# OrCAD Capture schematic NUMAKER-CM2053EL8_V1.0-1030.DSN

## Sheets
1 Nu-Link2-Me: size A3; title: Nu-Link2-Me; rev: 1.1; company: HCTu; note: Nu-Link2-Me
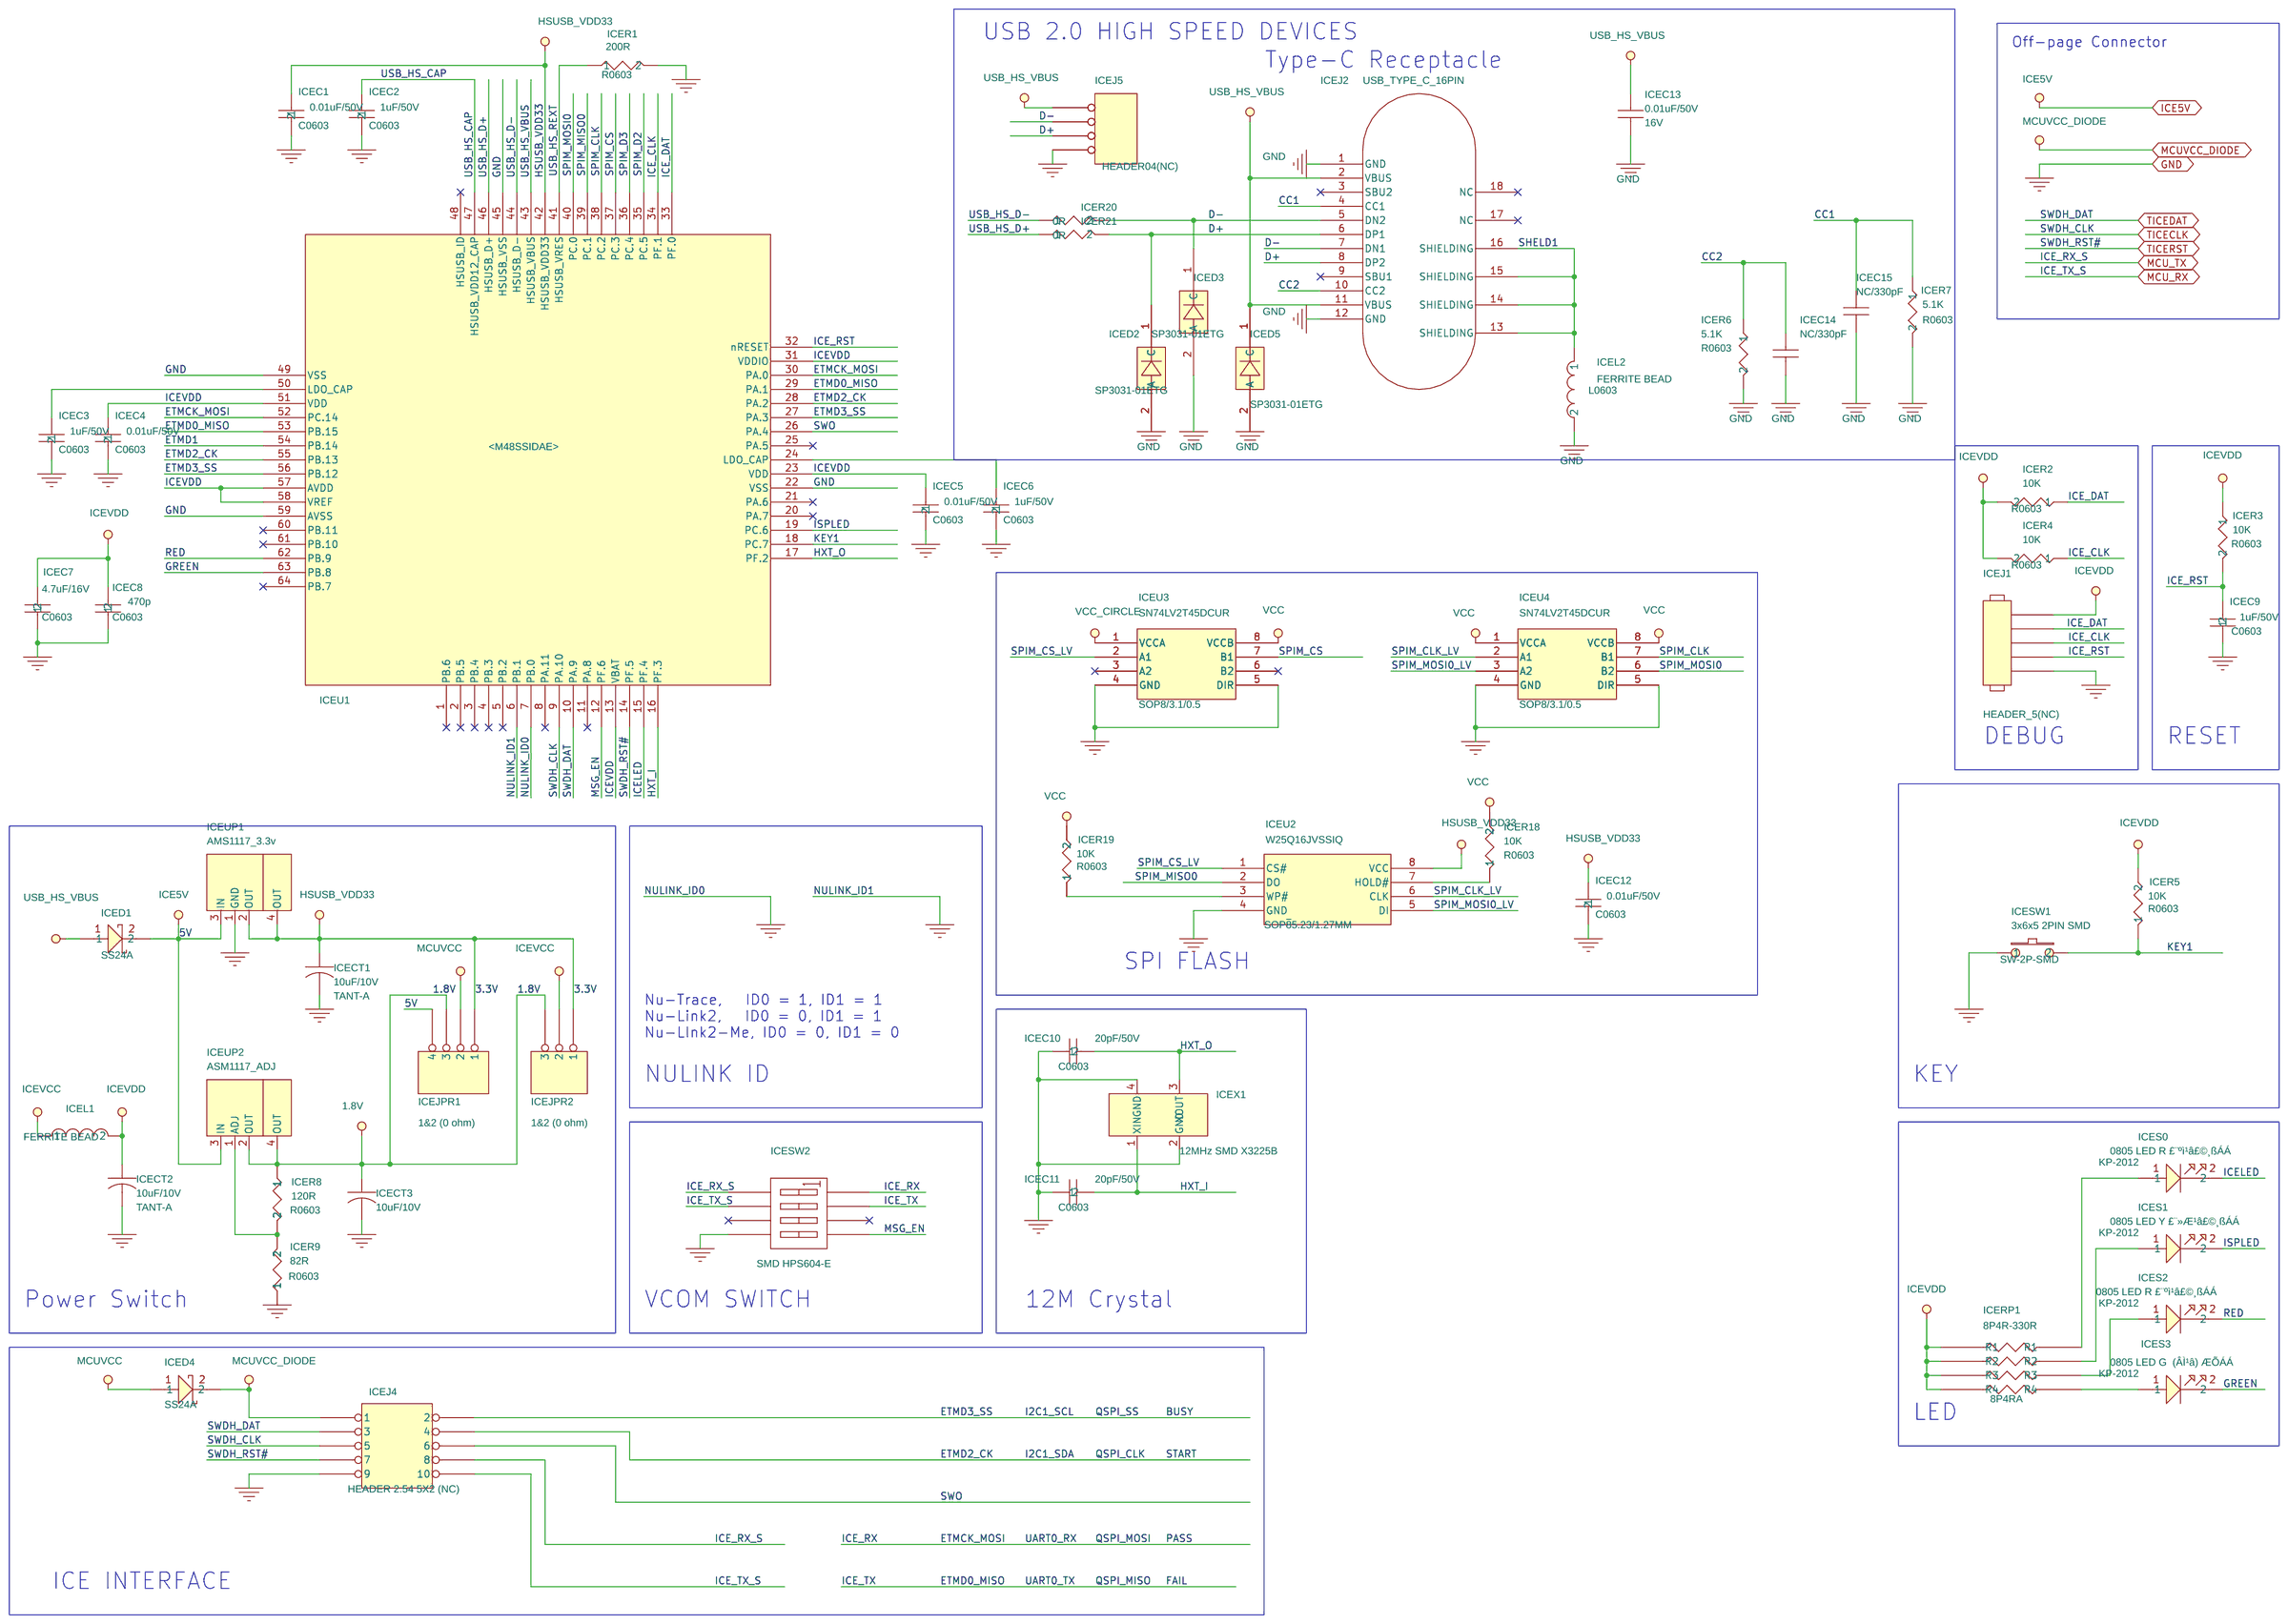
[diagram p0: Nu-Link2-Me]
2 CM2053EL8AE: size Custom; title: CM2053EL8AE; rev: v1.0; note: NuMaker-CM2053EL8
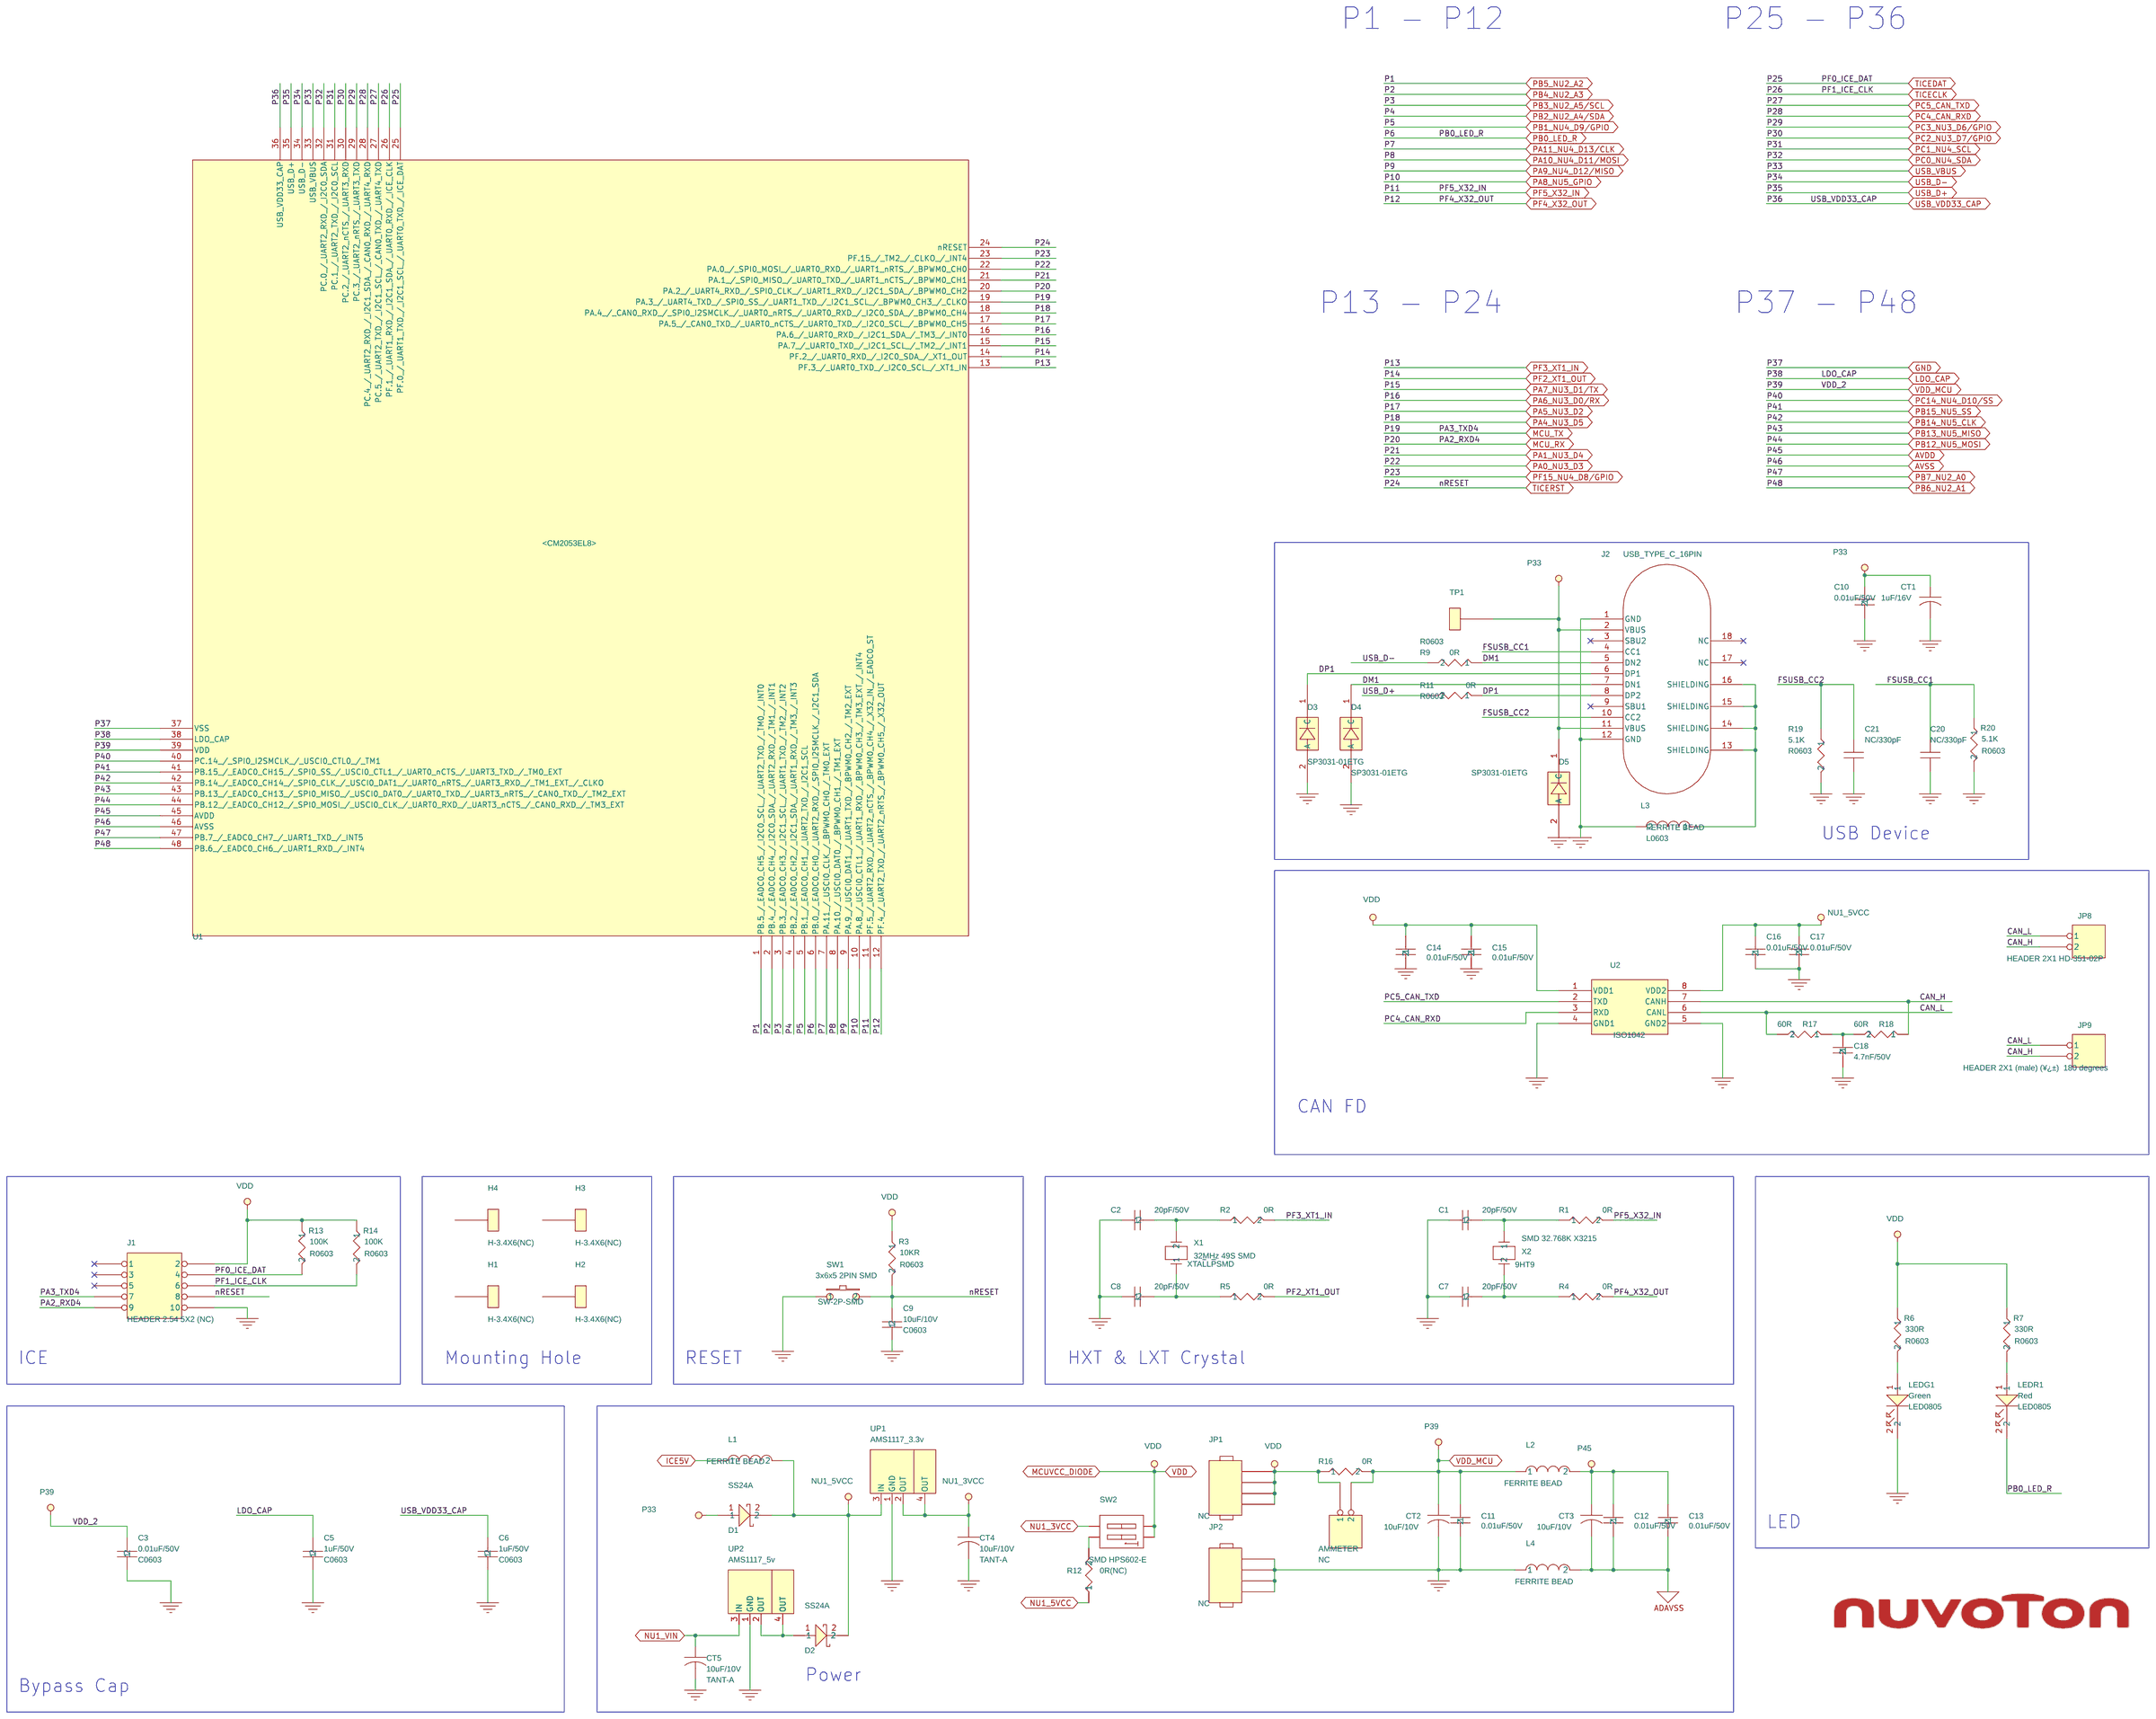
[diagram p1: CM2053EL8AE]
3 Ext. Connector: size Custom; title: Ext. Connector; rev: v1.0; note: NuMaker-CM2053EL8
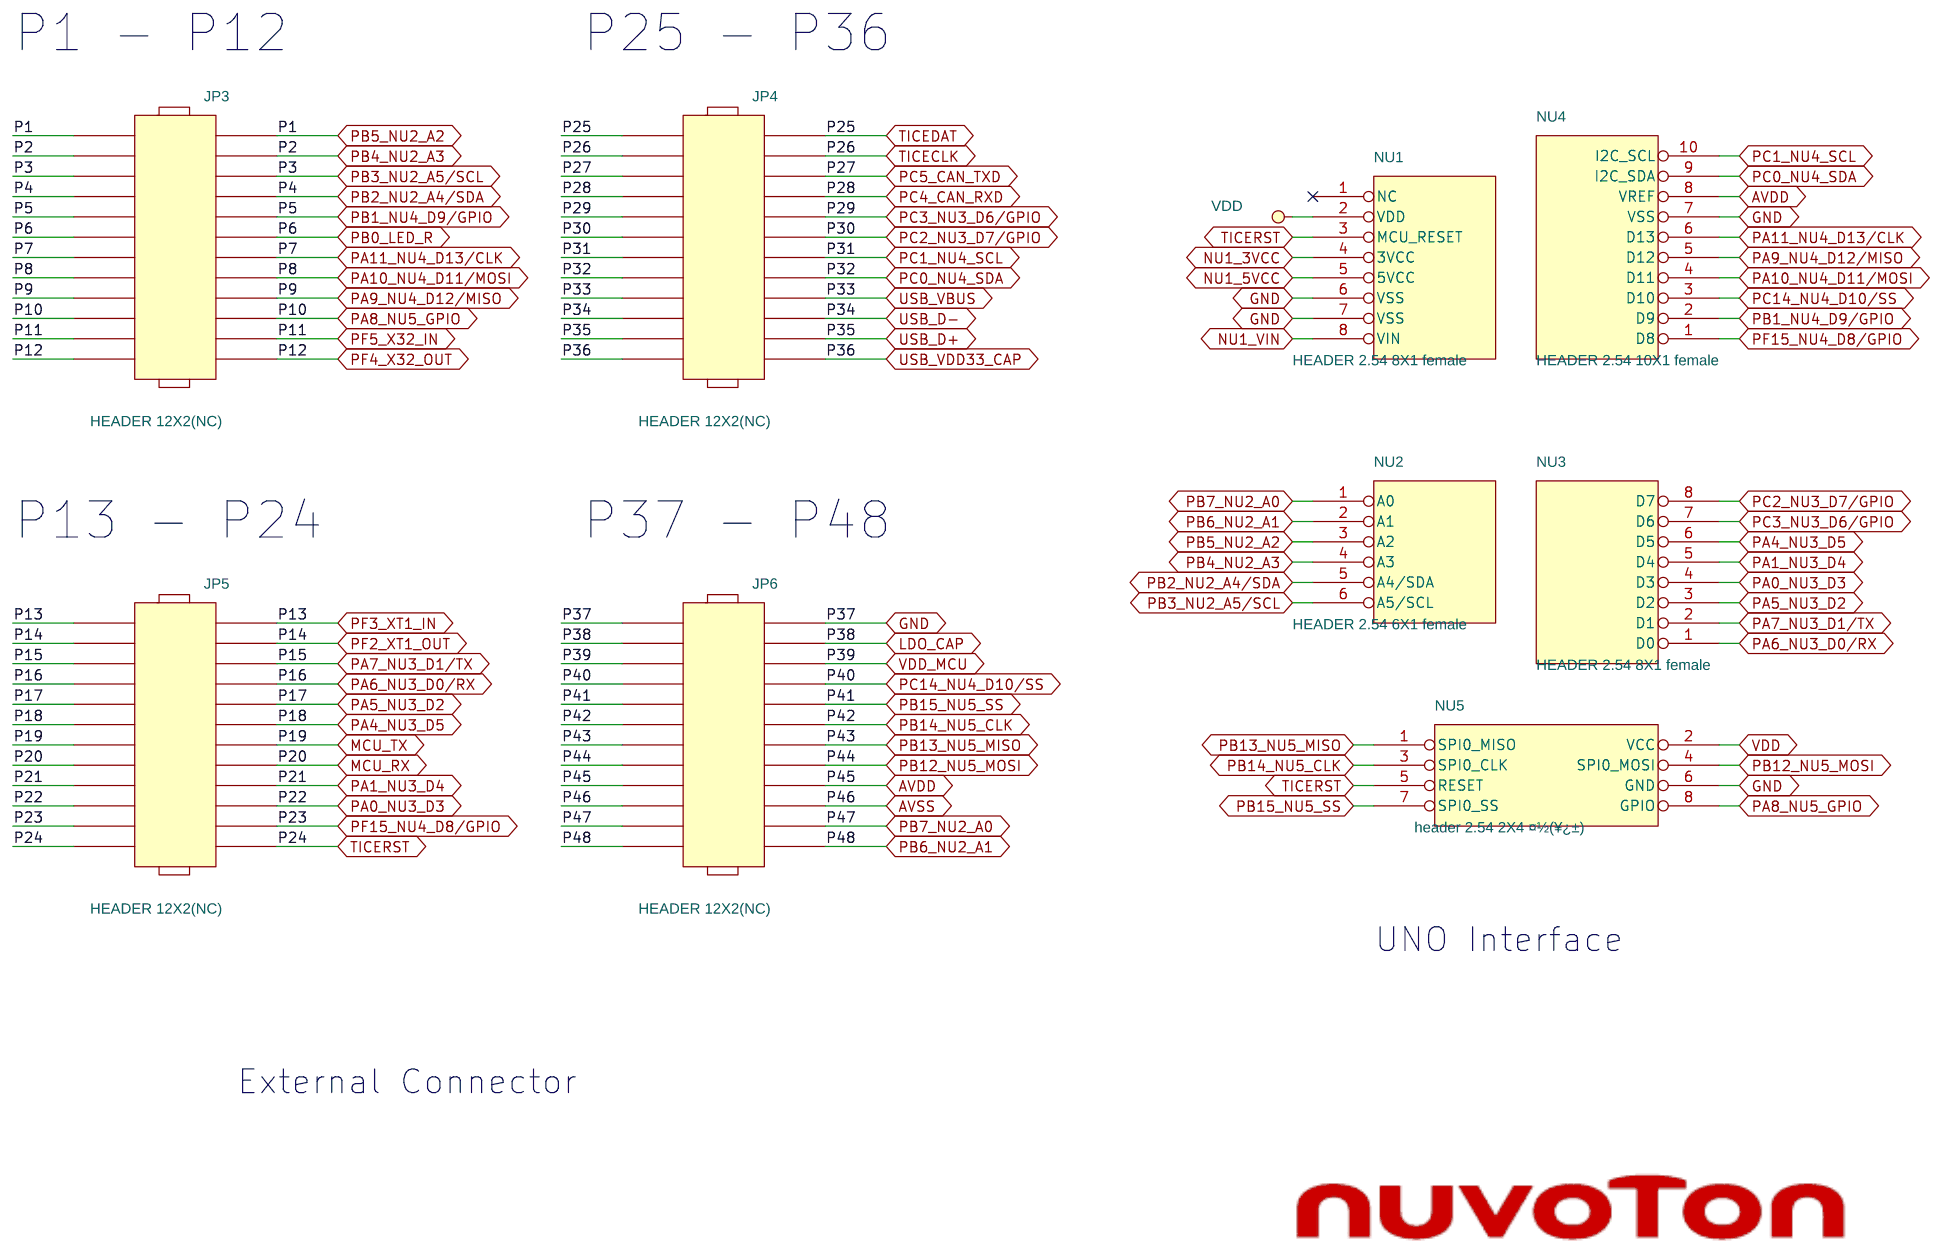
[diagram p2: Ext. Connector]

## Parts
sheet CM2053EL8AE
AMMETER  NC  [HEADER2X1]
C1  20pF/50V  [C0603]
C2  20pF/50V  [C0603]
C3  0.01uF/50V  [C0603]
C5  1uF/50V  [C0603]
C6  1uF/50V  [C0603]
C7  20pF/50V  [C0603]
C8  20pF/50V  [C0603]
C9  10uF/10V  [C0603]
C10  0.01uF/50V  [C0603]
C11  0.01uF/50V  [C0603]
C12  0.01uF/50V  [C0603]
C13  0.01uF/50V  [C0603]
C14  0.01uF/50V  [C0603]
C15  0.01uF/50V  [C0603]
C16  0.01uF/50V  [C0603]
C17  0.01uF/50V  [C0603]
C18  4.7nF/50V  [C0603]
C20  NC/330pF  [C0603]
C21  NC/330pF  [C0603]
CT1  1uF/16V  [TANT-A]
CT2  10uF/10V  [TANT-A]
CT3  10uF/10V  [TANT-A]
CT4  10uF/10V  [TANT-A]
CT5  10uF/10V  [TANT-A]
D1  SS24A  [RB060L]
D2  SS24A  [RB060L]
D3  SP3031-01ETG  [SOD882]
D4  SP3031-01ETG  [SOD882]
D5  SP3031-01ETG  [SOD882]
H1  H-3.4X6(NC)  [H-3.4X6]
H2  H-3.4X6(NC)  [H-3.4X6]
H3  H-3.4X6(NC)  [H-3.4X6]
H4  H-3.4X6(NC)  [H-3.4X6]
J1  HEADER 2.54 5X2 (NC)  [HEADER5X2]
J2  USB_TYPE_C_16PIN  [TID(00302-UCAF003-N)]
JP1  NC  [header1x4]
JP2  NC  [header1x4]
JP8  HEADER 2X1 HD-351-02P  [SIP/2P_3.5MM]
JP9  HEADER 2X1 (male) (¥¿­±)  180 degrees  [SIP-2P]
L1  FERRITE BEAD  [L0603]
L2  FERRITE BEAD  [L0603]
L3  FERRITE BEAD  [L0603]
L4  FERRITE BEAD  [L0603]
LEDG1  Green  [LED0805]
LEDR1  Red  [LED0805]
R1  0R  [R0603]
R2  0R  [R0603]
R3  10KR  [R0603]
R4  0R  [R0603]
R5  0R  [R0603]
R6  330R  [R0603]
R7  330R  [R0603]
R9  0R  [R0603]
R11  0R  [R0603]
R12  0R(NC)  [R0603]
R13  100K  [R0603]
R14  100K  [R0603]
R16  0R  [R0603]
R17  60R  [R0603]
R18  60R  [R0603]
R19  5.1K  [R0603]
R20  5.1K  [R0603]
SW1  3x6x5 2PIN SMD  [SW-2P-SMD]
SW2  SMD HPS602-E  [SW1X2]
TP1  TEST_POINT  [TEST_POINT]
U1  CM2053EL8  [MCU_LQFP_48]
U2  ISO1042  [SOIC-2.8MM]
UP1  AMS1117_3.3v  [SOT-223-1]
UP2  AMS1117_5v  [SOT-223-1]
X1  32MHz 49S SMD  [XTAL\LP\SMD]
X2  SMD 32.768K X3215  [9HT9]
sheet Ext. Connector
JP3  HEADER 12X2(NC)  [HEADER12x2/2.54]
JP4  HEADER 12X2(NC)  [HEADER12x2/2.54]
JP5  HEADER 12X2(NC)  [HEADER12x2/2.54]
JP6  HEADER 12X2(NC)  [HEADER12x2/2.54]
NU1  HEADER 2.54 8X1 female  [SIP-8P]
NU2  HEADER 2.54 6X1 female  [SIP-6P]
NU3  HEADER 2.54 8X1 female  [SIP-8P]
NU4  HEADER 2.54 10X1 female  [SIP-10P]
NU5  header 2.54 2X4 ¤½(¥¿­±)  [HEADER4X2]
sheet Nu-Link2-Me
ICEC1  0.01uF/50V  [C0603]
ICEC2  1uF/50V  [C0603]
ICEC3  1uF/50V  [C0603]
ICEC4  0.01uF/50V  [C0603]
ICEC5  0.01uF/50V  [C0603]
ICEC6  1uF/50V  [C0603]
ICEC7  4.7uF/16V  [C0603]
ICEC8  470p  [C0603]
ICEC9  1uF/50V  [C0603]
ICEC10  20pF/50V  [C0603]
ICEC11  20pF/50V  [C0603]
ICEC12  0.01uF/50V  [C0603]
ICEC13  0.01uF/50V  [C0603]
ICEC14  NC/330pF  [C0603]
ICEC15  NC/330pF  [C0603]
ICECT1  10uF/10V  [TANT-A]
ICECT2  10uF/10V  [TANT-A]
ICECT3  10uF/10V  [TANT-A]
ICED1  SS24A  [RB060L]
ICED2  SP3031-01ETG  [SOD882]
ICED3  SP3031-01ETG  [SOD882]
ICED4  SS24A  [RB060L]
ICED5  SP3031-01ETG  [SOD882]
ICEJ1  HEADER_5(NC)  [HEADER5X1]
ICEJ2  USB_TYPE_C_16PIN  [TID(00302-UCAF003-N)]
ICEJ4  HEADER 2.54 5X2 (NC)  [HEADER5X2]
ICEJ5  HEADER04(NC)  [HEADER04]
ICEJPR1  1&2 (0 ohm)  [R0603X3]
ICEJPR2  1&2 (0 ohm)  [R0603X2]
ICEL1  FERRITE BEAD  [L0603]
ICEL2  FERRITE BEAD  [L0603]
ICER1  200R  [R0603]
ICER2  10K  [R0603]
ICER3  10K  [R0603]
ICER4  10K  [R0603]
ICER5  10K  [R0603]
ICER6  5.1K  [R0603]
ICER7  5.1K  [R0603]
ICER8  120R  [R0603]
ICER9  82R  [R0603]
ICER18  10K  [R0603]
ICER19  10K  [R0603]
ICER20  0R  [R0603]
ICER21  0R  [R0603]
ICERP1  8P4R-330R  [8P4RA]
ICES0  0805 LED R £¨ºì¹â£©¸ßÁÁ  [KP-2012]
ICES1  0805 LED Y £¨»Æ¹â£©¸ßÁÁ  [KP-2012]
ICES2  0805 LED R £¨ºì¹â£©¸ßÁÁ  [KP-2012]
ICES3  0805 LED G  (ÂÌ¹â) ÆÕÁÁ  [KP-2012]
ICESW1  3x6x5 2PIN SMD  [SW-2P-SMD]
ICESW2  SMD HPS604-E  [SW1X4]
ICEU1  M48SSIDAE  [LQFP64_7x7_M48SSIDAE]
ICEU2  W25Q16JVSSIQ  [SOP8\5.23/1.27MM]
ICEU3  SN74LV2T45DCUR  [SOP8/3.1/0.5]
ICEU4  SN74LV2T45DCUR  [SOP8/3.1/0.5]
ICEUP1  AMS1117_3.3v  [SOT-223-1]
ICEUP2  ASM1117_ADJ  [SOT-223-1]
ICEX1  12MHz SMD X3225B  [CRYSTAL_SMD]

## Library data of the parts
AMMETER = HEADER_2_2
C1 = C_20p_2
C2 = C_20p
C3 = CAP-C_2: Package: 0603; element_no: C0004
C5 = CAP-C_1: Package: 0603; element_no: C0006
C6 = CAP-C: Package: 0603; element_no: C0006
C7 = C_20p_1
C8 = C_20p_3
C9 ICEC6 = CAP-C_3: Package: 0603; element_no: C0006
C10 = C_0.1u_6: element_no: C0004
C11 = C_0.1u: element_no: C0004
C12 = C_0.1u_2: element_no: C0004
C13 = C_0.1u_8: element_no: C0003
C14 = C_0.1u_3: element_no: C0004
C15 = C_0.1u_7: element_no: C0003
C16 = C_0.1u_1: element_no: C0004
C17 = C_0.1u_4: element_no: C0003
C18 = C_0.1u_5: element_no: C0003
C20 C21 ICEC14 ICEC15 = CAPACITOR_NP: CAP CER NPO SMD 330pF 5% 50V 0603; Mount: M; Part Number: 880600252; Part Type: Capacitor\Ceramic; Raing/Power: 50V; Tolerance: 5%
CT1 = C_1uF_16V
CT2-CT5 ICECT1-ICECT3 = C_10uF_10V
D1 ICED1 = D_SS24A
D2 ICED4 = D_SS24A_1
D3-D5 ICED2 ICED3 ICED5 = Schottky_Barrier_Diode_1: Diode SMD Schottky Barrier 30V; Mount: M; Part Number: 880900908
H1-H4 TP1 = TEST_POINT
ICEJ4 J1 = HEADER_5X2
ICEJ2 J2 = USB_TYPE_C_10: CON USB 3.0 Type C receptical SMD & TH; Mount: M; Part Number: 880400981; Part Type: Connector
JP1 JP2 = HEADER_4_v2
JP8 = HEADER_2_1
JP9 = HEADER_2
L1 = FERRITE_BEAD_2
L2 = FERRITE_BEAD_3
ICEL2 L3 = FERRITE_BEAD
ICEL1 L4 = FERRITE_BEAD_1
LEDG1 = LED_0_1: Package: KP-2012; Vendor: Kingbright
LEDR1 = LED_0: Package: KP-2012; Vendor: Kingbright
R1 = R_0_13
R2 = R_0_1
ICER8 R3 = R_0_3: Package: 0603
R4 = R_0_10
R5 = R_0_14
ICER3 R6 = R_0_6: Package: 0603
ICER5 R7 = R_0: Package: 0603
R9 = R_0_9
R11 = R_0_11
R12 = R_0_2
ICER1 R13 = R_0_5: Package: 0603
ICER18 R14 = R_0_7: Package: 0603
R16 = R_0_12
ICER20 R17 = R_33_1
ICER21 R18 = R_33
ICER6 R19 = R_0_4: Package: 0603
ICER7 R20 = R_0_8: Package: 0603
ICESW1 SW1 = SW_PUSHBUTTON_0
SW2 = SW_DIP-4_2
U1 = M032LD2AE_1: M032LD2AE: <CM2053EL8>
U2 = ADM3050
ICEUP1 UP1 UP2 = TO-247_Regulator_10
X1 = Xtal_12MHz
X2 = Xtal_32.768K
JP3-JP6 = HEADER_12X2
NU1 = POWER_CONNECT_0
NU2 = ADC_CONNECT_0
NU3 = PWM0_CONNECT_0
NU4 = PWM1_CONNECT_1
NU5 = NuEdu_NU7
ICEC1 = CAP-C_8: Package: 0603; element_no: C0004
ICEC2 = CAP-C_9: Package: 0603; element_no: C0006
ICEC3 = CAP-C_11: Package: 0603; element_no: C0006
ICEC4 = CAP-C_1: Package: 0603; element_no: C0004
ICEC5 = CAP-C_4: Package: 0603; element_no: C0004
ICEC7 = CAP-C: Package: 0603
ICEC8 = CAP-C_6: Package: 0603
ICEC9 = CAP-C_5: Package: 0603; element_no: C0006
ICEC10 = CAP-C_2: Package: 0603
ICEC11 = CAP-C_10: Package: 0603
ICEC12 = CAP-C_7: Package: 0603; element_no: C0004
ICEC13 = CAPACITOR_NP: CAP CER X7R SMD 0.1uF 10% 50V 0603; Mount: M; Part Number: 880600286; Part Type: Capacitor\Ceramic; Raing/Power: 16V; Tolerance: 10%
ICEJ1 = HEADER_5
ICEJ5 = HEADER_4
ICEJPR1 = HEADER_3_0
ICEJPR2 = HEADER_3
ICER2 = R_0_2: Package: 0603
ICER4 = R_0_9: Package: 0603
ICER9 = R_0_10: Package: 0603
ICER19 = R_0_1: Package: 0603
ICERP1 = R-PACK8_0
ICES0 = LED_0_3: Vendor: Kingbright
ICES1 = LED_0: Vendor: Kingbright
ICES2 = LED_0_1: Vendor: Kingbright
ICES3 = LED_0_2: Vendor: Kingbright
ICESW2 = SW_DIP-4_SM
ICEU1 = M487SIDAE_0: M487SIDAE: <M48SSIDAE>
ICEU2 = W25P10_20_40_SOIC_0: Package: SOP8; Vendor: WINBOND
ICEU3 ICEU4 = SN74LV2T45
ICEUP2 = TO-247_Regulator_0
ICEX1 = Crystal_SMD_1

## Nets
1.8V: ICECT3.1 ICEJPR1.3 ICEJPR2.3 ICER8.1 ICEUP2.2(OUT) ICEUP2.4(OUT)
3.3V: ICEC1.1 ICEC12.1 ICECT1.1 ICEJPR1.1 ICEJPR2.1 ICER18.2 ICER19.2 ICEU1.42(HSUSB_VDD33) ICEU2.8(VCC) ICEU3.1(VCCA) ICEU4.1(VCCA) ICEUP1.2(OUT) ICEUP1.4(OUT)
AVDD: C12.1 C13.1 CT3.1 JP6.17 JP6.18 L2.2 NU4.8(VREF) U1.45(AVDD)
AVSS: C12.2 C13.2 CT3.2 JP6.19 JP6.20 L4.2 U1.46(AVSS)
GND: C1.1 C2.1 C3.1 C5.1 C6.1 C7.1 C8.1 C9.1 C10.2 C11.2 C14.2 C15.2 C16.2 C17.2 C18.2 C20.2 C21.2 CT1.2 CT2.2 CT4.2 CT5.2 D3.2(A) D4.2(A) D5.2(A) ICEC1.2 ICEC2.2 ICEC3.2 ICEC4.2 ICEC5.2 ICEC6.2 ICEC7.1 ICEC8.1 ICEC9.1 ICEC10.1 ICEC11.1 ICEC12.2 ICEC13.2 ICEC14.2 ICEC15.2 ICECT1.2 ICECT2.2 ICECT3.2 ICED2.2(A) ICED3.2(A) ICED5.2(A) ICEJ1.5 ICEJ2.1(GND) ICEJ2.12(GND) ICEJ4.9 ICEJ5.4 ICEL2.2 ICER1.2 ICER6.2 ICER7.2 ICER9.1 ICESW1.1 ICESW2.4(A4) ICEU1.6(PB.1) ICEU1.7(PB.0) ICEU1.22(VSS) ICEU1.45(HSUSB_VSS) ICEU1.49(VSS) ICEU1.59(AVSS) ICEU2.4(GND) ICEU3.4(GND) ICEU3.5(DIR) ICEU4.4(GND) ICEU4.5(DIR) ICEUP1.1(GND) ICEX1.2(GND) ICEX1.4(GND) J1.10 J2.1(GND) J2.12(GND) JP2.1 JP2.2 JP2.3 JP2.4 JP6.1 JP6.2 L3.2 L4.1 LEDG1.2 NU1.6(VSS) NU1.7(VSS) NU4.7(VSS) NU5.6(GND) R19.2 R20.2 SW1.1 U1.37(VSS) U2.4(GND1) U2.5(GND2) UP1.1(GND) UP2.1(GND)
VDD: AMMETER.1 C14.1 C15.1 ICED4.2 ICEJ4.1 J1.2 JP1.1 JP1.2 JP1.3 JP1.4 NU1.2(VDD) NU5.2(VCC) R3.1 R6.1 R7.1 R13.1 R14.1 R16.1 SW2.3(B1) SW2.4(B2) U2.1(VDD1)
VDD_MCU: AMMETER.2 C3.2 C11.1 CT2.1 JP6.5 JP6.6 L2.1 R16.2 U1.39(VDD)
BUSY: ICEJ4.2 ICEU1.27(PA.3) ICEU1.56(PB.12)
CAN_H: JP8.2 JP9.2 R18.1 U2.7(CANH)
CAN_L: JP8.1 JP9.1 R17.2 U2.6(CANL)
CC1: ICEC15.1 ICEJ2.4(CC1) ICER7.1
CC2: ICEC14.1 ICEJ2.10(CC2) ICER6.1
D+: ICED2.1(C) ICEJ2.6(DP1) ICEJ2.8(DP2) ICEJ5.3 ICER21.2
D-: ICED3.1(C) ICEJ2.5(DN2) ICEJ2.7(DN1) ICEJ5.2 ICER20.2
DM1: D4.1(C) J2.5(DN2) J2.7(DN1) R9.1
DP1: D3.1(C) J2.6(DP1) J2.8(DP2) R11.1
ETMD1: ICEU1.54(PB.14)
ETMD2_CK: ICEJ4.4 ICEU1.28(PA.2) ICEU1.55(PB.13)
FSUSB_CC1: C20.1 J2.4(CC1) R20.1
FSUSB_CC2: C21.1 J2.10(CC2) R19.1
GREEN: ICES3.2 ICEU1.63(PB.8)
HXT_I: ICEC11.2 ICEU1.16(PF.3) ICEX1.1(XIN)
HXT_O: ICEC10.2 ICEU1.17(PF.2) ICEX1.3(XOUT)
ICE5V: ICED1.2 ICEJPR1.4 ICEUP1.3(IN) ICEUP2.3(IN) L1.1
ICE_CLK: ICEJ1.3 ICER4.1 ICEU1.34(PF.1)
ICE_DAT: ICEJ1.2 ICER2.1 ICEU1.33(PF.0)
ICE_RST: ICEC9.2 ICEJ1.4 ICER3.2 ICEU1.32(nRESET)
ICE_RX: ICESW2.8(B1) ICEU1.30(PA.0) ICEU1.52(PC.14)
ICE_TX: ICESW2.7(B2) ICEU1.29(PA.1) ICEU1.53(PB.15)
ICELED: ICES0.2 ICEU1.15(PF.4)
ICEVCC: ICEJPR2.2 ICEL1.1
ICEVDD: ICEC4.1 ICEC5.1 ICEC7.2 ICEC8.2 ICECT2.1 ICEJ1.1 ICEL1.2 ICER2.2 ICER3.1 ICER4.2 ICER5.2 ICERP1.1(R1) ICERP1.3(R2) ICERP1.5(R3) ICERP1.7(R4) ICEU1.13(VBAT) ICEU1.23(VDD) ICEU1.31(VDDIO) ICEU1.51(VDD) ICEU1.57(AVDD) ICEU1.58(VREF) ICEU3.8(VCCB) ICEU4.8(VCCB)
ISPLED: ICES1.2 ICEU1.19(PC.6)
KEY1: ICER5.1 ICESW1.2 ICEU1.18(PC.7)
LDO_CAP: C5.2 JP6.3 JP6.4 U1.38(LDO_CAP)
MCU_RX: ICEJ4.10 ICESW2.2(A2) J1.9 JP5.15 JP5.16 U1.20(PA.2_/_UART4_RXD_/_SPI0_CLK_/_UART1_RXD_/_I2C1_SDA_/_BPWM0_CH2)
MCU_TX: ICEJ4.8 ICESW2.1(A1) J1.7 JP5.13 JP5.14 U1.19(PA.3_/_UART4_TXD_/_SPI0_SS_/_UART1_TXD_/_I2C1_SCL_/_BPWM0_CH3_/_CLKO)
MCUVCC: ICED4.1 ICEJPR1.2
MSG_EN: ICESW2.5(B4) ICEU1.12(PF.6)
NU1_3VCC: CT4.1 NU1.4(3VCC) SW2.2(A2) UP1.2(OUT) UP1.4(OUT)
NU1_5VCC: C16.1 C17.1 D1.2 D2.2 L1.2 NU1.5(5VCC) R12.1 U2.8(VDD2) UP1.3(IN)
NU1_VIN: CT5.1 NU1.8(VIN) UP2.3(IN)
PA0_NU3_D3: JP5.19 JP5.20 NU3.4(D3) U1.22(PA.0_/_SPI0_MOSI_/_UART0_RXD_/_UART1_nRTS_/_BPWM0_CH0)
PA1_NU3_D4: JP5.17 JP5.18 NU3.5(D4) U1.21(PA.1_/_SPI0_MISO_/_UART0_TXD_/_UART1_nCTS_/_BPWM0_CH1)
PA4_NU3_D5: JP5.11 JP5.12 NU3.6(D5) U1.18(PA.4_/_CAN0_RXD_/_SPI0_I2SMCLK_/_UART0_nRTS_/_UART0_RXD_/_I2C0_SDA_/_BPWM0_CH4)
PA5_NU3_D2: JP5.9 JP5.10 NU3.3(D2) U1.17(PA.5_/_CAN0_TXD_/_UART0_nCTS_/_UART0_TXD_/_I2C0_SCL_/_BPWM0_CH5)
PA6_NU3_D0/RX: JP5.7 JP5.8 NU3.1(D0) U1.16(PA.6_/_UART0_RXD_/_I2C1_SDA_/_TM3_/_INT0)
PA7_NU3_D1/TX: JP5.5 JP5.6 NU3.2(D1) U1.15(PA.7_/_UART0_TXD_/_I2C1_SCL_/_TM2_/_INT1)
PA8_NU5_GPIO: JP3.19 JP3.20 NU5.8(GPIO) U1.10(PA.8_/_USCI0_CTL1_/_UART1_RXD_/_BPWM0_CH3_/_TM3_EXT_/_INT4)
PA9_NU4_D12/MISO: JP3.17 JP3.18 NU4.5(D12) U1.9(PA.9_/_USCI0_DAT1_/_UART1_TXD_/_BPWM0_CH2_/_TM2_EXT)
PA10_NU4_D11/MOSI: JP3.15 JP3.16 NU4.4(D11) U1.8(PA.10_/_USCI0_DAT0_/_BPWM0_CH1_/_TM1_EXT)
PA11_NU4_D13/CLK: JP3.13 JP3.14 NU4.6(D13) U1.7(PA.11_/_USCI0_CLK_/_BPWM0_CH0_/_TM0_EXT)
PB0_LED_R: JP3.11 JP3.12 LEDR1.2 U1.6(PB.0_/_EADC0_CH0_/_UART2_RXD_/_SPI0_I2SMCLK_/_I2C1_SDA)
PB1_NU4_D9/GPIO: JP3.9 JP3.10 NU4.2(D9) U1.5(PB.1_/_EADC0_CH1_/_UART2_TXD_/_I2C1_SCL)
PB2_NU2_A4/SDA: JP3.7 JP3.8 NU2.5(A4/SDA) U1.4(PB.2_/_EADC0_CH2_/_I2C1_SDA_/_UART1_RXD_/_TM3_/_INT3)
PB3_NU2_A5/SCL: JP3.5 JP3.6 NU2.6(A5/SCL) U1.3(PB.3_/_EADC0_CH3_/_I2C1_SCL_/_UART1_TXD_/_TM2_/_INT2)
PB4_NU2_A3: JP3.3 JP3.4 NU2.4(A3) U1.2(PB.4_/_EADC0_CH4_/_I2C0_SDA_/_UART2_RXD_/_TM1_/_INT1)
PB5_NU2_A2: JP3.1 JP3.2 NU2.3(A2) U1.1(PB.5_/_EADC0_CH5_/_I2C0_SCL_/_UART2_TXD_/_TM0_/_INT0)
PB6_NU2_A1: JP6.23 JP6.24 NU2.2(A1) U1.48(PB.6_/_EADC0_CH6_/_UART1_RXD_/_INT4)
PB7_NU2_A0: JP6.21 JP6.22 NU2.1(A0) U1.47(PB.7_/_EADC0_CH7_/_UART1_TXD_/_INT5)
PB12_NU5_MOSI: JP6.15 JP6.16 NU5.4(SPI0_MOSI) U1.44(PB.12_/_EADC0_CH12_/_SPI0_MOSI_/_USCI0_CLK_/_UART0_RXD_/_UART3_nCTS_/_CAN0_RXD_/_TM3_EXT)
PB13_NU5_MISO: JP6.13 JP6.14 NU5.1(SPI0_MISO) U1.43(PB.13_/_EADC0_CH13_/_SPI0_MISO_/_USCI0_DAT0_/_UART0_TXD_/_UART3_nRTS_/_CAN0_TXD_/_TM2_EXT)
PB14_NU5_CLK: JP6.11 JP6.12 NU5.3(SPI0_CLK) U1.42(PB.14_/_EADC0_CH14_/_SPI0_CLK_/_USCI0_DAT1_/_UART0_nRTS_/_UART3_RXD_/_TM1_EXT_/_CLKO)
PB15_NU5_SS: JP6.9 JP6.10 NU5.7(SPI0_SS) U1.41(PB.15_/_EADC0_CH15_/_SPI0_SS_/_USCI0_CTL1_/_UART0_nCTS_/_UART3_TXD_/_TM0_EXT)
PC0_NU4_SDA: JP4.15 JP4.16 NU4.9(I2C_SDA) U1.32(PC.0_/_UART2_RXD_/_I2C0_SDA)
PC1_NU4_SCL: JP4.13 JP4.14 NU4.10(I2C_SCL) U1.31(PC.1_/_UART2_TXD_/_I2C0_SCL)
PC2_NU3_D7/GPIO: JP4.11 JP4.12 NU3.8(D7) U1.30(PC.2_/_UART2_nCTS_/_UART3_RXD)
PC3_NU3_D6/GPIO: JP4.9 JP4.10 NU3.7(D6) U1.29(PC.3_/_UART2_nRTS_/_UART3_TXD)
PC4_CAN_RXD: JP4.7 JP4.8 U1.28(PC.4_/_UART2_RXD_/_I2C1_SDA_/_CAN0_RXD_/_UART4_RXD) U2.3(RXD)
PC5_CAN_TXD: JP4.5 JP4.6 U1.27(PC.5_/_UART2_TXD_/_I2C1_SCL_/_CAN0_TXD_/_UART4_TXD) U2.2(TXD)
PC14_NU4_D10/SS: JP6.7 JP6.8 NU4.3(D10) U1.40(PC.14_/_SPI0_I2SMCLK_/_USCI0_CTL0_/_TM1)
PF2_XT1_OUT: JP5.3 JP5.4 R5.2 U1.14(PF.2_/_UART0_RXD_/_I2C0_SDA_/_XT1_OUT)
PF3_XT1_IN: JP5.1 JP5.2 R2.2 U1.13(PF.3_/_UART0_TXD_/_I2C0_SCL_/_XT1_IN)
PF4_X32_OUT: JP3.23 JP3.24 R4.2 U1.12(PF.4_/_UART2_TXD_/_UART2_nRTS_/_BPWM0_CH5_/_X32_OUT)
PF5_X32_IN: JP3.21 JP3.22 R1.2 U1.11(PF.5_/_UART2_RXD_/_UART2_nCTS_/_BPWM0_CH4_/_X32_IN_/_EADC0_ST)
PF15_NU4_D8/GPIO: JP5.21 JP5.22 NU4.1(D8) U1.23(PF.15_/_TM2_/_CLKO_/_INT4)
RED: ICES2.2 ICEU1.62(PB.9)
SHELD1: ICEJ2.13(SHIELDING) ICEJ2.14(SHIELDING) ICEJ2.15(SHIELDING) ICEJ2.16(SHIELDING) ICEL2.1
SPIM_CLK: ICEU1.38(PC.2) ICEU4.7(B1)
SPIM_CLK_LV: ICEU2.6(CLK) ICEU4.2(A1)
SPIM_CS: ICEU1.37(PC.3) ICEU3.7(B1)
SPIM_CS_LV: ICEU2.1(CS#) ICEU3.2(A1)
SPIM_D2: ICEU1.35(PC.5)
SPIM_D3: ICEU1.36(PC.4)
SPIM_MISO0: ICEU1.39(PC.1) ICEU2.2(DO)
SPIM_MOSI0: ICEU1.40(PC.0) ICEU4.6(B2)
SPIM_MOSI0_LV: ICEU2.5(DI) ICEU4.3(A2)
SWO: ICEJ4.6 ICEU1.26(PA.4)
TICECLK: ICEJ4.5 ICEU1.9(PA.10) J1.6 JP4.3 JP4.4 R14.2 U1.26(PF.1_/_UART1_RXD_/_I2C1_SDA_/_UART0_RXD_/_ICE_CLK)
TICEDAT: ICEJ4.3 ICEU1.10(PA.9) J1.4 JP4.1 JP4.2 R13.2 U1.25(PF.0_/_UART1_TXD_/_I2C1_SCL_/_UART0_TXD_/_ICE_DAT)
TICERST: C9.2 ICEJ4.7 ICEU1.14(PF.5) J1.8 JP5.23 JP5.24 NU1.3(MCU_RESET) NU5.5(RESET) R3.2 SW1.2 U1.24(nRESET)
USB_D+: JP4.21 JP4.22 R11.2 U1.35(USB_D+)
USB_D-: JP4.19 JP4.20 R9.2 U1.34(USB_D-)
USB_HS_CAP: ICEC2.1 ICEU1.47(HSUSB_VDD12_CAP)
USB_HS_D+: ICER21.1 ICEU1.46(HSUSB_D+)
USB_HS_D-: ICER20.1 ICEU1.44(HSUSB_D-)
USB_HS_REXT: ICER1.1 ICEU1.41(HSUSB_VRES)
USB_HS_VBUS: ICEC13.1 ICED1.1 ICED5.1(C) ICEJ2.2(VBUS) ICEJ2.11(VBUS) ICEJ5.1 ICEU1.43(HSUSB_VBUS)
USB_VBUS: C10.1 CT1.1 D1.1 D5.1(C) J2.2(VBUS) J2.11(VBUS) JP4.17 JP4.18 TP1.1 U1.33(USB_VBUS)
USB_VDD33_CAP: C6.2 JP4.23 JP4.24 U1.36(USB_VDD33_CAP)
N16825237: LEDG1.1 R6.2
N16825240: LEDR1.1 R7.2
N16840819: ICEC6.1 ICEU1.24(LDO_CAP)
N16840960: ICEC3.1 ICEU1.50(LDO_CAP)
N17019924: ICER8.2 ICER9.2 ICEUP2.1(ADJ)
N17029977: ICERP1.8(R4) ICES3.1
N17029979: ICERP1.6(R3) ICES2.1
N17030004: ICERP1.4(R2) ICES1.1
N17030010: ICERP1.2(R1) ICES0.1
N17155328: ICER18.1 ICEU2.7(HOLD#)
N17155343: ICER19.1 ICEU2.3(WP#)
N17187930: R12.2 SW2.1(A1)
N17187980: D2.1 UP2.2(OUT) UP2.4(OUT)
N17237210: C8.2 R5.1 X1.1
N17237212: C2.2 R2.1 X1.2
N17237304: C1.2 R1.1 X2.1
N17237306: C7.2 R4.1 X2.2
N17249439: C18.1 R17.1 R18.2
N17281368: J2.13(SHIELDING) J2.14(SHIELDING) J2.15(SHIELDING) J2.16(SHIELDING) L3.1

Not connected (* = marked no-connect by the designer): H1 1; H2 1; H3 1; H4 1; ICEJ2 3(SBU2)* 9(SBU1)* 17(NC)* 18(NC)*; ICESW2 3(A3)* 6(B3)*; ICEU1 1(PB.6)* 2(PB.5)* 3(PB.4)* 4(PB.3)* 5(PB.2)* 8(PA.11)* 11(PA.8)* 20(PA.7)* 21(PA.6)* 25(PA.5)* 48(HSUSB_ID)* 60(PB.11)* 61(PB.10)* 64(PB.7)*; ICEU3 3(A2)* 6(B2)*; J1 1* 3* 5*; J2 3(SBU2)* 9(SBU1)* 17(NC)* 18(NC)*; NU1 1(NC)*

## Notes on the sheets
sheet 1
- USB 2.0 HIGH SPEED DEVICES
- Type-C Receptacle
- Off-page Connector
- DEBUG
- RESET
- SPI FLASH
- Nu-Trace,   ID0 = 1, ID1 = 1
  Nu-Link2,   ID0 = 0, ID1 = 1
  Nu-LInk2-Me, ID0 = 0, ID1 = 0
- NULINK ID
- KEY
- Power Switch
- VCOM SWITCH
- 12M Crystal
- LED
- ICE INTERFACE
sheet 2
- P1 - P12
- P25 - P36
- P13 - P24
- P37 - P48
- USB Device
- CAN FD
- ICE
- Mounting Hole
- RESET
- HXT & LXT Crystal
- LED
- Power
- Bypass Cap
sheet 3
- P1 - P12
- P25 - P36
- P13 - P24
- P37 - P48
- UNO Interface
- External Connector
